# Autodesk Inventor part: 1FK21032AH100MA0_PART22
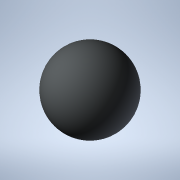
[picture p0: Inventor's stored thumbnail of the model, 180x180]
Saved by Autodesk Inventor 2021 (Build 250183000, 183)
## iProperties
Created: 2025-04
Part Number: 1FK21032AH100MA0_PART22
Material: Generic
Catalog Web Link: www.3dfindit.com
Description: -Servo synchronous motor
Document SubType Name: Modeling
Designer: psAdmin
Mass: 0.113097 g
Surface Area: 1.13097 cm^2
Volume: 0.113097 cm^3
Density: 1 g/cm^3
Appearance: PSOLRGB-212-217-219
Category: PARTsolutions
Title: 1FK21032AH100MA0_PART22
Author: Cadenas PARTsolutions
Comments: Servo synchronous motor
Sending System: PARTsolutions
Preprocessor: ST-DEVELOPER v19.3
PSOL_IDENT_0: {$CADENAS_DATA/23d-libs/siemens_ag/_cat_/12/33/1fk21032ah100ma0.prj},216 {VTYP=3D},{NB=1FK21032AH100
PSOL_IDENT_1: MA0_PART22},{LINA=1FK21032AH100MA0_PART22},{NN=1FK21032AH100MA0_PART22},{NOPRJ=TRUE},{DATE=19.08.202
PSOL_IDENT_2: 5 14:00:27},{GEOMDATE=30.07.2025 02:02:58},{VERSION=},{LINEID=10},{WBVAR=},{WBNUMERIC=}  {NB=1FK2103
PSOL_IDENT_3: 2AH100MA0_PART22},{LINA=1FK21032AH100MA0_PART22},{KT=DUMMY},{PREVIEW=../../../_pool_/d3/78/p_d211_xx
PSOL_IDENT_4: _00934j.png},{DESCSHORT=SIMOTICS S-1FK2 HD, SINAMICS S210 3AC 400V-480V, 0.59 Nm, 4500 rpm},{DESCLON
PSOL_IDENT_5: G=SIMOTICS S-1FK2 HD servo motor M0=0.64 Nm; PN = 0.28 kW at nN=4500 rpm (380-480 V); PN = 0.167 kW
PSOL_IDENT_6: at nN=2500 rpm (200-240 V); with holding brake; degree of protection IP64; cylindrical shaft D14 x 3
PSOL_IDENT_7: 0 mm; absolute encoder 22-bit + 12-bit multiturn (encoder AM22DQC); with OCC interface; plug size M1
PSOL_IDENT_8: 7, rotatable; SIMOTICS S-1FK2 servomotorfor a wide range of uses in industrial environments. SIMOTIC
PSOL_IDENT_9: S S‑1FK2 servomotors are compact synchronous motors with a high dynamic performance that set themsel
PSOL_IDENT_10: ves apart as a result of their high power density, degree of protection and overload capability. The
PSOL_IDENT_11: motors are available in two variants: as High Dynamic variant (highest dynamic performance as a res
PSOL_IDENT_12: ult of the low intrinsic moment of inertia for applications demanding a high dynamic performance wit
PSOL_IDENT_13: h low moved masses) - and as Compact variant (precise and stable closed-loop control for medium up t
PSOL_IDENT_14: o large moved masses as a result of a medium intrinsic moment of inertia). SIMOTICSS‑1FK2 servomotor
PSOL_IDENT_15: s fully exploit their strengths in a system with the SINAMICSS210 frequency converter and simple con
PSOL_IDENT_16: nection using the one cable connection (OCC). Advantages include the short control and positioning t
PSOL_IDENT_17: imes, fast and precise correction of disturbing quantities as well as stable control with a high dyn
PSOL_IDENT_18: amic performance. The servo motors can be configured to address a wide range of requirements. For ex
PSOL_IDENT_19: ample with and without holding brake, IP64 or IP65 degree of protection, singleturn or multiturn abs
PSOL_IDENT_20: olute encoders - to name just a few. Further, the servomotors are available in different shaft heigh
PSOL_IDENT_21: ts extending from 20 to 100. A shaft sealing ring is available to achieve an IP65 degree of protecti
PSOL_IDENT_22: on and for subsequent mounting at the motor or as spare part. SIMOTICS - the optimum motor for each
PSOL_IDENT_23: and every motion control application.},{INTNO=195125315563},{SUPPLIERALTNO=1FK2103-2AH10-0MA0},{MANU
PSOL_IDENT_24: ID=1FK21032AH100MA0},{MANUNAME=Siemens},{MANUTYPEDESC=SYNCHRONOUS MOTOR 1FK2 HD 0,64 NM},{AAU732=SIM
PSOL_IDENT_25: OTICS},{AAO057=S-1FK2},{AAU734=SIMOTICS S-1FK2 HD servo motor M0=0.64 Nm; PN = 0.28 kW at nN=4500 rp
PSOL_IDENT_26: m (380-480 V); PN = 0.167 kW at nN=2500 rpm (200-240 V); with holding brake; degree of protection IP
PSOL_IDENT_27: 64; cylindrical shaft D14 x 30 mm; absolute encoder 22-bit + 12-bit multiturn (encoder AM22DQC); wit
PSOL_IDENT_28: h OCC interface; plug size M17, rotatable;},{AAW338=SYNCHRONOUS MOTOR 1FK2 HD 0,64 NM},{AAO742=SIMOT
PSOL_IDENT_29: ICS},{AAO663=4034106444723},{NOCUPEROU=1},{PRICEQUANTITY=1},{QUANTITYMIN=1},{QUANTITYINT=1},{CTN=850
PSOL_IDENT_30: 15100},{COO=RO},{AAO676=1FK2103-2AH10-0MA0},{AAO677=Siemens AG},{ORDERUNIT=C62},{CONTENTUNIT=C62}
NB: 1FK21032AH100MA0_PART22
NT: Servo synchronous motor
NBSYN: $MANUID._PART22
LINA: 1FK21032AH100MA0_PART22
CATALOG: SIEMENS
PREVIEW: ../../../_pool_/d3/78/p_d211_xx_00934j.png
DESCSHORT: SIMOTICS S-1FK2 HD, SINAMICS S210 3AC 400V-480V, 0.59 Nm, 4500 rpm
DESCLONG: SIMOTICS S-1FK2 HD servo motor M0=0.64 Nm; PN = 0.28 kW at nN=4500 rpm (380-480 V); PN = 0.167 kW at nN=2500 rpm (200-240 V); with holding brake; degree of prot
INTNO: 195125315563
SUPPLIERALTNO: 1FK2103-2AH10-0MA0
MANUID: 1FK21032AH100MA0
MANUNAME: Siemens
MANUTYPEDESC: SYNCHRONOUS MOTOR 1FK2 HD 0,64 NM
AAU732: SIMOTICS
AAO057: S-1FK2
AAU734: SIMOTICS S-1FK2 HD servo motor M0=0.64 Nm; PN = 0.28 kW at nN=4500 rpm (380-480 V); PN = 0.167 kW at nN=2500 rpm (200-240 V); with holding brake; degree of prot
AAW338: SYNCHRONOUS MOTOR 1FK2 HD 0,64 NM
AAO742: SIMOTICS
AAO663: 4034106444723.0
NOCUPEROU: 1
PRICEQUANTITY: 1
QUANTITYMIN: 1
QUANTITYINT: 1
CTN: 85015100
COO: RO
ARTICLENO: 1FK21032AH100MA0_PART22
BOMINFO: 1FK21032AH100MA0_PART22
CREATOR: CADENAS GmbH
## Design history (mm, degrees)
feature "2025_04_17_15_06_16_0705"
body "Solid1"
